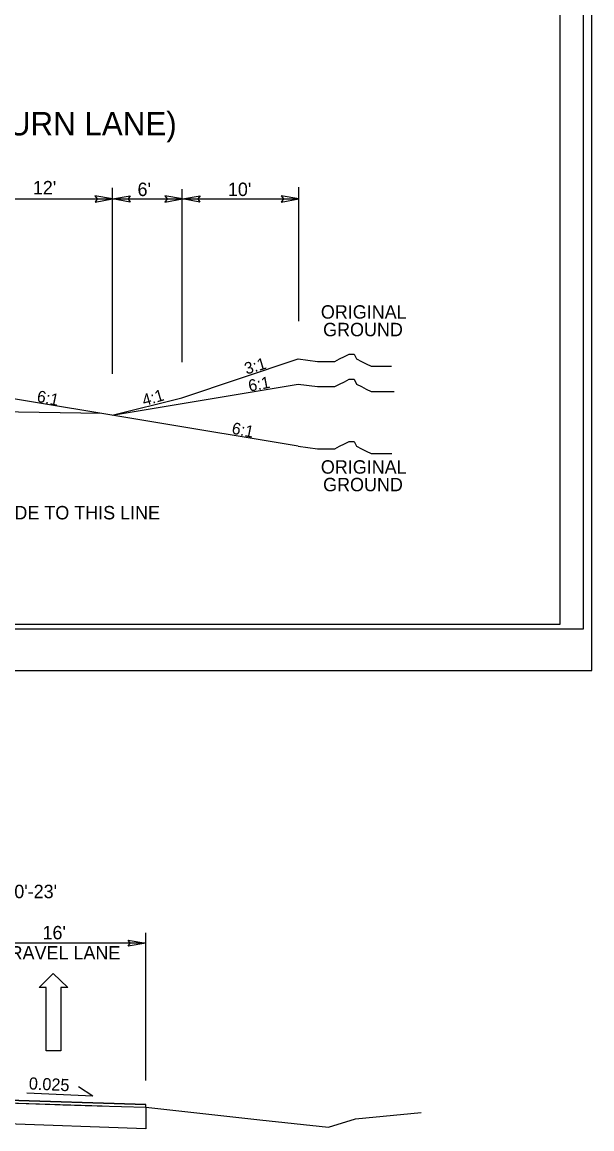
# Model space of a CAD drawing. Extents: x 2176156 to 2177167, y 76401 to 76644.
# Drawn here: x 2176849.7 to 2176898.7, y 76415.1 to 76510.2 of the extents above; entities that cross this region are included whole.
import ezdxf

# ---------------------------------------------------------------- set-up
doc = ezdxf.new("R2010")
doc.units = 0
for name, color, linetype in [('Exist Building', 7, 'Continuous'), ('Exist Roads Curbs', 7, 'Continuous'), ('Exist Roads EOP Other', 7, 'Continuous'), ('Exist Roads Soil', 7, 'Continuous'), ('Exist Structure Minor Culvert Topo', 7, 'Continuous'), ('Exist Structure Minor Drop Inlet', 7, 'Continuous'), ('Exist Utilities Other Pole CELL', 7, 'Continuous'), ('Exist Vegetation Woods Line', 7, 'Continuous'), ('Old_Level_1', 7, 'Continuous'), ('Old_Level_3', 7, 'Continuous'), ('Sheet Cutting Line CELL', 7, 'Continuous'), ('Sheet Data Field CELL', 7, 'Continuous'), ('Sheet Plan CELL', 7, 'Continuous'), ('Sheet Plot Border Outside CELL', 7, 'Continuous'), ('Sheet Sticker Exception Certification CELL', 7, 'Continuous')]:
    doc.layers.add(name, color=color, linetype=linetype)

msp = doc.modelspace()

# ---------------------------------------------------------------- linework, layer by layer
at = {"layer": 'Exist Building'}
msp.add_line((2176856.606, 76476.559), (2176833.533, 76476.902), dxfattribs=at)
at = {"layer": 'Exist Roads Curbs'}
for p, q in [((2176836.359, 76417.701), (2176856.626, 76417.069)), ((2176844.366, 76417.701), (2176860.366, 76417.202)), ((2176860.366, 76417.202), (2176844.366, 76417.701)), ((2176844.366, 76417.451), (2176852.548, 76417.196)), ((2176860.366, 76416.952), (2176860.366, 76417.202))]:
    msp.add_line(p, q, dxfattribs=at)
for points in [[(2176873.471, 76481.248), (2176875.141, 76481.04), (2176875.559, 76481.04), (2176876.186, 76481.04), (2176876.604, 76481.04), (2176877.022, 76481.248), (2176877.439, 76481.458), (2176877.857, 76481.667), (2176878.274, 76481.667), (2176878.484, 76481.248), (2176878.902, 76481.04), (2176879.319, 76480.83), (2176879.737, 76480.622), (2176880.155, 76480.622), (2176880.572, 76480.622), (2176880.99, 76480.622), (2176881.408, 76480.622), (2176881.477, 76480.622)], [(2176873.471, 76479.081), (2176875.141, 76478.873), (2176875.559, 76478.873), (2176876.186, 76478.873), (2176876.604, 76478.873), (2176877.022, 76479.081), (2176877.439, 76479.291), (2176877.857, 76479.501), (2176878.275, 76479.501), (2176878.484, 76479.081), (2176878.902, 76478.873), (2176879.32, 76478.664), (2176879.737, 76478.456), (2176880.155, 76478.456), (2176880.573, 76478.456), (2176880.99, 76478.456), (2176881.408, 76478.456), (2176881.729, 76478.456)], [(2176873.471, 76473.748), (2176875.141, 76473.54), (2176875.559, 76473.54), (2176876.186, 76473.54), (2176876.604, 76473.54), (2176877.022, 76473.748), (2176877.439, 76473.958), (2176877.857, 76474.167), (2176878.274, 76474.167), (2176878.484, 76473.748), (2176878.902, 76473.54), (2176879.319, 76473.33), (2176879.737, 76473.122), (2176880.155, 76473.122), (2176880.572, 76473.122), (2176880.99, 76473.122), (2176881.408, 76473.122), (2176881.502, 76473.122)], [(2176852.548, 76417.196), (2176853.236, 76417.175), (2176854.234, 76417.144), (2176855.174, 76417.114), (2176856.193, 76417.082), (2176860.366, 76416.952)]]:
    msp.add_lwpolyline(points, dxfattribs=at)
at = {"layer": 'Exist Roads EOP Other'}
for p, q in [((2176863.471, 76477.915), (2176873.471, 76481.248)), ((2176857.471, 76476.415), (2176863.471, 76477.915))]:
    msp.add_line(p, q, dxfattribs=at)
at = {"layer": 'Exist Roads Soil'}
for p, q in [((2176873.471, 76473.748), (2176845.519, 76478.407)), ((2176857.471, 76476.415), (2176873.471, 76479.081))]:
    msp.add_line(p, q, dxfattribs=at)
at = {"layer": 'Exist Structure Minor Drop Inlet'}
for p, q in [((2176851.214, 76427.23), (2176852.416, 76428.452)), ((2176852.416, 76428.452), (2176853.658, 76427.23)), ((2176851.796, 76427.23), (2176851.214, 76427.23)), ((2176851.796, 76421.798), (2176851.796, 76427.23)), ((2176853.658, 76427.23), (2176853.076, 76427.23)), ((2176853.076, 76427.23), (2176853.076, 76421.798)), ((2176853.076, 76421.798), (2176851.796, 76421.798))]:
    msp.add_line(p, q, dxfattribs=at)
at = {"layer": 'Exist Utilities Other Pole CELL'}
for q in [(2176854.574, 76418.708), (2176850.135, 76418.177)]:
    msp.add_line((2176855.814, 76417.912), q, dxfattribs=at)
at = {"layer": 'Old_Level_1'}
for points in [[(2176856.009, 76494.732), (2176857.519, 76494.992), (2176856.001, 76495.261), (2176856.194, 76494.992)], [(2176859.028, 76494.732), (2176857.519, 76494.992), (2176859.037, 76495.261), (2176858.844, 76494.992)], [(2176862.009, 76494.732), (2176863.519, 76494.992), (2176862.001, 76495.261), (2176862.194, 76494.992)], [(2176865.028, 76494.732), (2176863.519, 76494.992), (2176865.037, 76495.261), (2176864.844, 76494.992)], [(2176872.009, 76494.732), (2176873.519, 76494.992), (2176872.001, 76495.261), (2176872.194, 76494.992)], [(2176858.857, 76431.325), (2176860.366, 76431.065), (2176858.848, 76430.796), (2176859.041, 76431.065)]]:
    msp.add_lwpolyline(points, close=True, dxfattribs=at)
at = {"layer": 'Old_Level_3'}
for p, q in [((2176857.506, 76479.965), (2176857.506, 76495.958)), ((2176863.506, 76480.983), (2176863.506, 76495.824)), ((2176873.52, 76484.482), (2176873.52, 76496.022)), ((2176845.519, 76494.992), (2176857.519, 76494.992)), ((2176857.519, 76494.992), (2176863.519, 76494.992)), ((2176863.519, 76494.992), (2176873.519, 76494.992)), ((2176860.366, 76419.252), (2176860.366, 76431.949)), ((2176860.366, 76431.065), (2176844.366, 76431.065))]:
    msp.add_line(p, q, dxfattribs=at)
at = {"layer": 'Sheet Cutting Line CELL'}
msp.add_lwpolyline([(2176898.707, 76630.475), (2176629.267, 76630.475), (2176629.267, 76454.475), (2176898.707, 76454.475)], close=True, dxfattribs=at)
at = {"layer": 'Sheet Data Field CELL'}
msp.add_lwpolyline([(2176895.987, 76626.475), (2176655.987, 76626.475), (2176655.987, 76458.475), (2176895.987, 76458.475)], close=True, dxfattribs=at)
at = {"layer": 'Sheet Plan CELL'}
for p, q in [((2176860.366, 76416.952), (2176860.366, 76415.098)), ((2176860.366, 76415.098), (2176835.691, 76415.992))]:
    msp.add_line(p, q, dxfattribs=at)
msp.add_lwpolyline([(2176860.366, 76416.952), (2176870.175, 76415.887), (2176876.086, 76415.244), (2176878.386, 76415.947), (2176884.043, 76416.495)], dxfattribs=at)
at = {"layer": 'Sheet Plot Border Outside CELL'}
msp.add_lwpolyline([(2176897.987, 76626.883), (2176631.347, 76626.883), (2176631.347, 76458.067), (2176897.987, 76458.067)], close=True, dxfattribs=at)
at = {"layer": 'Sheet Sticker Exception Certification CELL'}
msp.add_line((2176629.267, 76454.475), (2176898.707, 76454.475), dxfattribs=at)

# ---------------------------------------------------------------- texts
at = {"layer": 'Exist Roads Curbs'}
for s, rotation, p in [('3:1', 16.46494, (2176869.017, 76479.903)), ('6:1', 10.81682, (2176869.284, 76478.434)), ('6:1', 348.51345, (2176850.952, 76477.583)), ('4:1', 16.46494, (2176860.227, 76477.182)), ('6:1', 348.51345, (2176867.702, 76474.842))]:
    msp.add_text(s, height=1.0064, rotation=rotation, dxfattribs=at).set_placement(p)
at = {"layer": 'Exist Structure Minor Culvert Topo'}
for s, height, p in [("12' ", 1.1533, (2176850.665, 76495.388)), ("6'", 1.1533, (2176859.661, 76495.245)), ("10'", 1.1533, (2176867.426, 76495.245)), ('ORIGINAL', 1.1533, (2176875.416, 76484.71)), ('GROUND', 1.1533, (2176875.61, 76483.199)), ('ORIGINAL', 1.1533, (2176875.416, 76471.392)), ('GROUND', 1.1533, (2176875.61, 76469.88)), ('GRADE TO THIS LINE', 1.15334, (2176845.738, 76467.464)), ("VARIES 0'-23'", 1.15334, (2176842.984, 76434.918)), ("16'", 1.1533, (2176851.494, 76431.381)), ('TRAVEL LANE', 1.15334, (2176847.725, 76429.651))]:
    msp.add_text(s, height=height, dxfattribs=at).set_placement(p)
at = {"layer": 'Exist Utilities Other Pole CELL'}
msp.add_text('0.025', height=1.0429, rotation=357.3324, dxfattribs=at).set_placement((2176850.301, 76418.491))
at = {"layer": 'Exist Vegetation Woods Line'}
msp.add_text('C -L_RTL- (US 17 RT TURN LANE)', height=2.01314, dxfattribs=at).set_placement((2176820.098, 76500.455))

doc.saveas('drawing.dxf')
